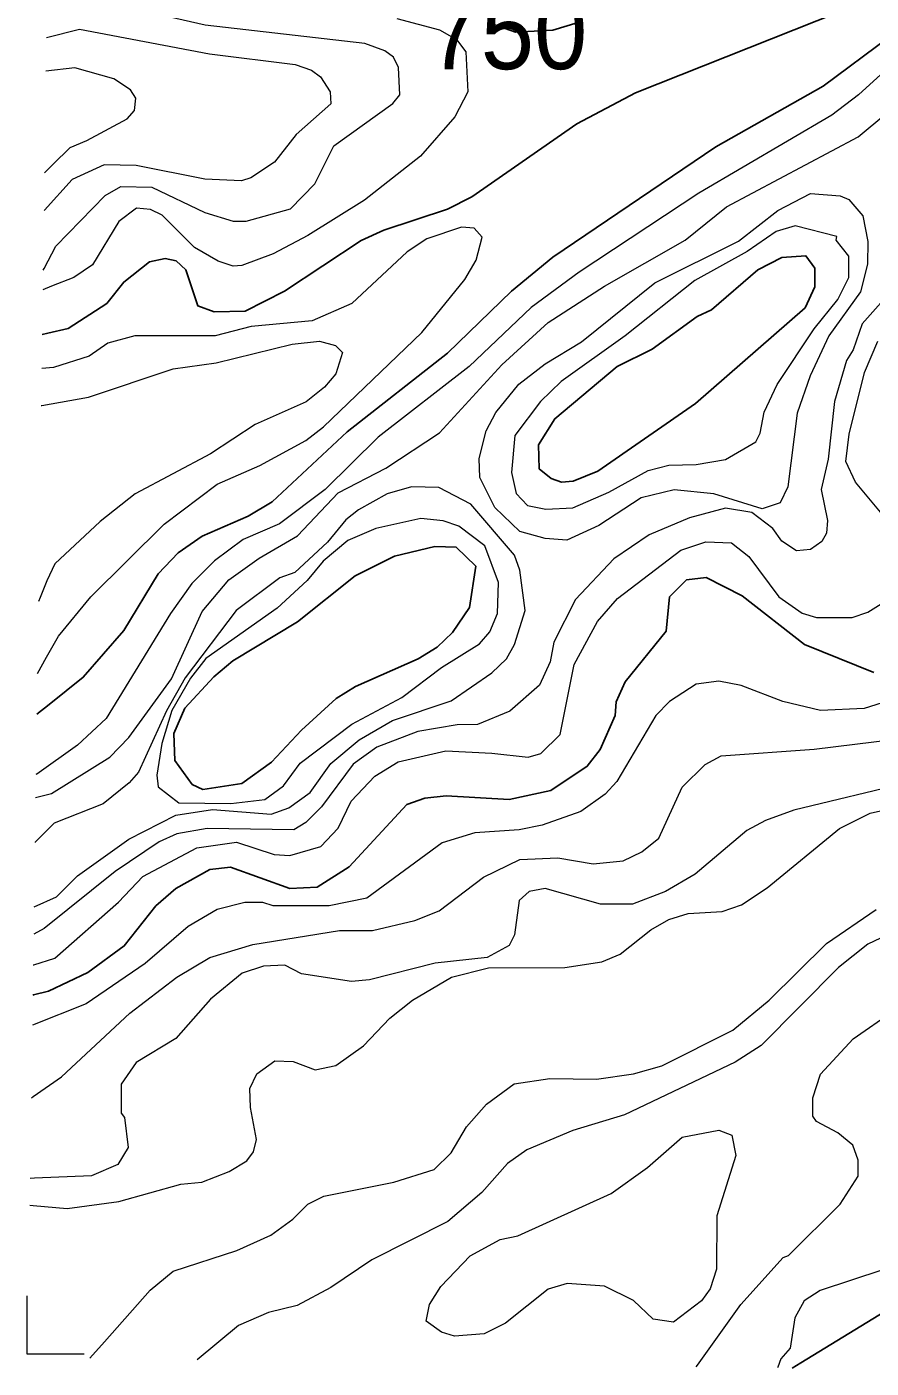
# Model space of a CAD drawing. Extents: x 763.2 to 816.8, y 7896.5 to 7952.7.
# Drawn here: x 763.19 to 764.982, y 7897.272 to 7900.119 of the extents above; entities that cross this region are included whole.
import ezdxf
from ezdxf.enums import TextEntityAlignment as Align

# ---------------------------------------------------------------- set-up
doc = ezdxf.new("R2010")
doc.units = 0
doc.header["$LTSCALE"] = 0.064
for name, color, linetype, lineweight in [('1', 7, 'Continuous', 25), ('2', 7, 'Continuous', 13), ('63', 7, 'Continuous', 13)]:
    doc.layers.add(name, color=color, linetype=linetype, lineweight=lineweight)
doc.layers.add('61', color=7, linetype='Continuous')

msp = doc.modelspace()

# ---------------------------------------------------------------- linework, layer by layer
at = {"layer": '1'}
for points in [[(765.2023, 7900.1889), (765.0206, 7900.0974), (764.8799, 7899.9927), (764.6523, 7899.8643), (764.3067, 7899.6301), (764.2184, 7899.5579), (764.0827, 7899.4258), (763.8702, 7899.2592), (763.7105, 7899.1107), (763.6598, 7899.0801), (763.562, 7899.0376), (763.5114, 7899.0022), (763.4688, 7898.9577), (763.3956, 7898.8377), (763.3097, 7898.7383), (763.2375, 7898.6808), (763.2112, 7898.6599)], [(763.2227, 7899.4656), (763.2344, 7899.4683), (763.2778, 7899.4783), (763.3598, 7899.5316), (763.3958, 7899.5769), (763.4504, 7899.6202), (763.4839, 7899.627), (763.5068, 7899.6222), (763.5276, 7899.6032), (763.5527, 7899.5264), (763.5876, 7899.5137), (763.6532, 7899.5152), (763.737, 7899.5574), (763.8997, 7899.6651), (763.9475, 7899.6872), (764.0828, 7899.7318), (764.1347, 7899.7579), (764.3572, 7899.9132), (764.4816, 7899.979), (764.9149, 7900.1509)], [(764.3602, 7900.1278), (764.3066, 7900.1116), (764.2273, 7900.1075), (764.1835, 7900.123)], [(763.2028, 7898.0637), (763.2039, 7898.064), (763.2363, 7898.0724), (763.3196, 7898.1114), (763.3967, 7898.1681), (763.464, 7898.2531), (763.5064, 7898.2898), (763.5785, 7898.3302), (763.6221, 7898.3351), (763.7485, 7898.2898), (763.8064, 7898.2928), (763.874, 7898.3362), (763.9966, 7898.4683), (764.0346, 7898.4817), (764.0798, 7898.4867), (764.2134, 7898.4786), (764.3023, 7898.4978), (764.3795, 7898.5493), (764.407, 7898.5848), (764.4384, 7898.6572), (764.4409, 7898.6864), (764.4602, 7898.7284), (764.5467, 7898.8363), (764.5541, 7898.9091), (764.5902, 7898.9452), (764.6315, 7898.9503), (764.7083, 7898.9108), (764.8408, 7898.8077), (764.9877, 7898.7483)], [(765.2865, 7898.4746), (765.2646, 7898.4497), (765.2575, 7898.4136), (765.263, 7898.4013), (765.3189, 7898.3901), (765.3894, 7898.4149), (765.5161, 7898.4868), (765.7045, 7898.6435), (765.7826, 7898.6814), (765.8542, 7898.6713), (765.8664, 7898.6475), (765.8457, 7898.5762), (765.7321, 7898.4812), (765.6742, 7898.4221), (765.615, 7898.3464), (765.5252, 7898.1825), (765.4318, 7898.0356), (765.3071, 7897.904), (765.206, 7897.7449), (765.1289, 7897.5484), (765.0877, 7897.4645), (765.0489, 7897.4158), (764.8329, 7897.2832), (764.8144, 7897.2719)]]:
    msp.add_lwpolyline(points, dxfattribs=at)
for points in [[(764.4427, 7899.3976), (764.5169, 7899.4348), (764.613, 7899.504), (764.6431, 7899.5178), (764.7418, 7899.6031), (764.7922, 7899.629), (764.8437, 7899.6325), (764.8622, 7899.6063), (764.8622, 7899.5667), (764.8418, 7899.5225), (764.6091, 7899.3196), (764.4016, 7899.1759), (764.3496, 7899.1546), (764.3245, 7899.1526), (764.303, 7899.1604), (764.2777, 7899.1804), (764.2761, 7899.2315), (764.3106, 7899.2871)], [(763.8874, 7898.7188), (764.0206, 7898.7773), (764.0608, 7898.8024), (764.0936, 7898.8336), (764.1296, 7898.8862), (764.1427, 7898.9741), (764.1009, 7899.0142), (764.0558, 7899.0157), (763.9703, 7898.9956), (763.8867, 7898.9535), (763.7642, 7898.8561), (763.627, 7898.7728), (763.5869, 7898.7394), (763.5254, 7898.6729), (763.5021, 7898.6189), (763.5041, 7898.5618), (763.541, 7898.5105), (763.5638, 7898.5003), (763.646, 7898.5131), (763.7096, 7898.558), (763.7728, 7898.6261), (763.8465, 7898.6933)]]:
    msp.add_lwpolyline(points, close=True, dxfattribs=at)
at = {"layer": '2'}
for points in [[(763.2247, 7899.6025), (763.2265, 7899.6059), (763.2519, 7899.653), (763.3563, 7899.7609), (763.3896, 7899.7796), (763.455, 7899.7788), (763.5677, 7899.7244), (763.6276, 7899.7063), (763.6553, 7899.7065), (763.7499, 7899.7328), (763.801, 7899.7852), (763.8414, 7899.8661), (763.9665, 7899.9559), (763.9817, 7899.9743), (763.9787, 7900.0326), (763.9683, 7900.0545), (763.9499, 7900.0681), (763.9075, 7900.0831), (763.5684, 7900.122), (763.4064, 7900.159), (763.3564, 7900.1779), (763.3128, 7900.1619), (763.2325, 7900.1554)], [(763.9752, 7900.1367), (764.066, 7900.1126), (764.1017, 7900.0922), (764.1216, 7900.0659), (764.1262, 7899.9811), (764.0981, 7899.9276), (764.0258, 7899.8439), (763.9067, 7899.7511), (763.7865, 7899.6759), (763.7127, 7899.6373), (763.6464, 7899.6122), (763.6281, 7899.611), (763.5961, 7899.6212), (763.546, 7899.6507), (763.4773, 7899.7193), (763.4528, 7899.7307), (763.4225, 7899.7341), (763.385, 7899.7056), (763.3297, 7899.6133), (763.2896, 7899.587), (763.2424, 7899.5682), (763.2241, 7899.5609)], [(763.2087, 7898.4828), (763.2423, 7898.4919), (763.3662, 7898.5685), (763.4065, 7898.6101), (763.497, 7898.7351), (763.562, 7898.8776), (763.6188, 7898.9453), (763.6828, 7898.9913), (763.7643, 7899.0387), (763.8511, 7899.1295), (763.9523, 7899.1821), (764.0661, 7899.2567), (764.1982, 7899.4016), (764.2963, 7899.4911), (764.4163, 7899.5685), (764.5871, 7899.666), (764.6749, 7899.7365), (764.9543, 7899.885), (765.0129, 7899.9338), (765.0931, 7900.0264), (765.1185, 7900.0452), (765.1961, 7900.0734), (765.2881, 7900.119)], [(763.2317, 7900.096), (763.3015, 7900.1137), (763.5779, 7900.0614), (763.7596, 7900.0387), (763.7939, 7900.0269), (763.8132, 7900.0128), (763.8336, 7899.981), (763.8352, 7899.955), (763.7614, 7899.8901), (763.716, 7899.8317), (763.6657, 7899.798), (763.6459, 7899.7918), (763.5678, 7899.7951), (763.422, 7899.8241), (763.3541, 7899.826), (763.286, 7899.7945), (763.2276, 7899.7293), (763.2265, 7899.728)], [(765.1723, 7900.1208), (765.0898, 7900.0971), (764.9548, 7899.9742), (764.8989, 7899.9315)], [(763.2276, 7899.8086), (763.2455, 7899.8265), (763.2819, 7899.8628), (763.3174, 7899.8777), (763.4033, 7899.9235), (763.4183, 7899.9411), (763.4214, 7899.9672), (763.4098, 7899.9852), (763.3744, 7900.0082), (763.2916, 7900.0315), (763.2306, 7900.0243)], [(764.8989, 7899.9315), (764.6163, 7899.7654), (764.3621, 7899.5981), (764.2603, 7899.5229), (764.1285, 7899.3978), (763.936, 7899.2477)], [(763.2125, 7898.7466), (763.2318, 7898.7806), (763.2574, 7898.8257), (763.3262, 7898.9092), (763.4818, 7899.0632), (763.5943, 7899.1483), (763.6842, 7899.1876), (763.7825, 7899.2407), (763.8196, 7899.2696), (764.0284, 7899.4702), (764.1195, 7899.5825), (764.1434, 7899.6238), (764.1561, 7899.6721), (764.1394, 7899.6912), (764.1128, 7899.6932), (764.0392, 7899.669), (763.9972, 7899.6411), (763.8795, 7899.5315), (763.7959, 7899.4947), (763.6664, 7899.4826), (763.5896, 7899.4632), (763.4192, 7899.4628), (763.3621, 7899.4471), (763.3221, 7899.4201), (763.2463, 7899.3959), (763.2217, 7899.3936)], [(765.0361, 7899.5704), (764.9628, 7899.4887), (764.9437, 7899.4332), (764.9298, 7899.4107), (764.904, 7899.3239), (764.8906, 7899.2011), (764.8761, 7899.1367), (764.8891, 7899.0713), (764.8873, 7899.044), (764.8774, 7899.0261), (764.8531, 7899.0097), (764.8236, 7899.0064), (764.7923, 7899.0272), (764.7734, 7899.0543), (764.7286, 7899.0881), (764.6729, 7899.0973), (764.5965, 7899.0768), (764.5112, 7899.0405), (764.4356, 7898.9897), (764.3542, 7898.9032), (764.3083, 7898.8127), (764.3007, 7898.7711), (764.2784, 7898.7212), (764.2152, 7898.666), (764.1468, 7898.6382), (764.1031, 7898.6376), (764.0202, 7898.6229), (763.9331, 7898.5897), (763.8829, 7898.5538), (763.8155, 7898.4634), (763.782, 7898.4299), (763.7567, 7898.4147), (763.5731, 7898.4176), (763.5087, 7898.4061), (763.4709, 7898.389), (763.3777, 7898.326), (763.2268, 7898.2048), (763.2046, 7898.1929)], [(763.2206, 7899.3148), (763.2215, 7899.315), (763.321, 7899.3324), (763.5009, 7899.3928), (763.5916, 7899.4059), (763.7532, 7899.4452), (763.8115, 7899.4514), (763.845, 7899.4425), (763.8599, 7899.4277), (763.8457, 7899.3821), (763.8219, 7899.3541), (763.7826, 7899.3226), (763.6743, 7899.2747), (763.5796, 7899.2124), (763.4199, 7899.1277), (763.3455, 7899.0692), (763.2495, 7898.9787), (763.2326, 7898.9429), (763.2181, 7898.9076), (763.2147, 7898.8992)], [(765.009, 7899.0801), (764.949, 7899.1521), (764.9286, 7899.1964), (764.935, 7899.2542), (764.9679, 7899.3852), (764.996, 7899.4515)], [(763.936, 7899.2477), (763.823, 7899.1371), (763.7261, 7899.064), (763.6494, 7899.0304), (763.5882, 7898.9855), (763.5403, 7898.9376), (763.4946, 7898.8733), (763.3582, 7898.6507), (763.2975, 7898.5945), (763.2112, 7898.5329), (763.2094, 7898.5316)], [(763.2054, 7898.2507), (763.2059, 7898.2509), (763.2527, 7898.272), (763.2977, 7898.317), (763.4068, 7898.3946), (763.5063, 7898.4454), (763.5843, 7898.4573), (763.7084, 7898.4475), (763.7458, 7898.461), (763.7911, 7898.4936), (763.8352, 7898.5553), (763.8953, 7898.6055), (763.9661, 7898.6464), (764.0907, 7898.6879), (764.1769, 7898.7477), (764.2081, 7898.7773), (764.2249, 7898.8079), (764.248, 7898.8797), (764.2364, 7898.9657), (764.2253, 7898.9973), (764.1321, 7899.1058), (764.0641, 7899.141), (764.0063, 7899.1427), (763.955, 7899.1274), (763.8937, 7899.0936), (763.8674, 7899.0723), (763.8284, 7899.0253), (763.7587, 7898.9608), (763.7267, 7898.9492), (763.6343, 7898.8801), (763.5263, 7898.7368), (763.4862, 7898.6667), (763.4268, 7898.5372), (763.4074, 7898.514), (763.3519, 7898.4694), (763.2483, 7898.4283), (763.2079, 7898.3883), (763.2074, 7898.3878)], [(763.2037, 7898.1277), (763.2046, 7898.128), (763.2491, 7898.1424), (763.3847, 7898.261), (763.4359, 7898.3151), (763.5507, 7898.3764), (763.6349, 7898.3881), (763.715, 7898.3622), (763.7485, 7898.3603), (763.8141, 7898.3788), (763.8511, 7898.4183), (763.8786, 7898.4751), (763.9289, 7898.5283), (763.9781, 7898.5587), (764.0796, 7898.5819), (764.1768, 7898.5774), (764.2541, 7898.569), (764.2812, 7898.5765), (764.3217, 7898.6169), (764.3518, 7898.7654), (764.401, 7898.8566), (764.4435, 7898.9055), (764.5781, 7899.0083), (764.6313, 7899.0256), (764.6857, 7899.0238), (764.7226, 7898.9948), (764.7861, 7898.9088), (764.8355, 7898.8745), (764.866, 7898.8649), (764.9416, 7898.8649), (764.9751, 7898.8767), (765.0205, 7898.9044)], [(765.0434, 7898.6958), (764.9671, 7898.6717), (764.8746, 7898.6679), (764.7944, 7898.6871), (764.7062, 7898.7206), (764.6584, 7898.73), (764.6103, 7898.7236), (764.5543, 7898.687), (764.5252, 7898.6571), (764.4421, 7898.5172), (764.4173, 7898.4902), (764.3658, 7898.4537), (764.2837, 7898.4242), (764.235, 7898.4146), (764.1409, 7898.4079), (764.0713, 7898.3867), (763.9114, 7898.2697), (763.8314, 7898.2535), (763.7131, 7898.2535), (763.6911, 7898.26), (763.6526, 7898.2599), (763.5941, 7898.2451), (763.5322, 7898.2093), (763.4415, 7898.1307), (763.3157, 7898.0455), (763.2019, 7898)], [(765.2665, 7898.7412), (765.216, 7898.6496), (765.1688, 7898.5827), (765.1267, 7898.5457), (765.0647, 7898.5154), (764.8181, 7898.456)], [(763.1997, 7897.8456), (763.2035, 7897.8483), (763.2636, 7897.8905), (763.4089, 7898.0254), (763.5081, 7898.1018), (763.5783, 7898.1435), (763.6696, 7898.1712), (763.8537, 7898.2007), (763.9234, 7898.2011), (764.0133, 7898.2218), (764.0653, 7898.2428), (764.1595, 7898.3142), (764.2361, 7898.3516), (764.3171, 7898.3553), (764.3918, 7898.3422), (764.4559, 7898.349), (764.495, 7898.3676), (764.5312, 7898.3971), (764.5806, 7898.5051), (764.6298, 7898.5532), (764.6634, 7898.5718), (764.861, 7898.5856), (765.0337, 7898.6069)], [(763.1965, 7897.6176), (763.2036, 7897.617), (763.2759, 7897.611), (763.3855, 7897.6254), (763.5168, 7897.6622), (763.5612, 7897.6668), (763.6197, 7897.6895), (763.6569, 7897.7119), (763.671, 7897.7309), (763.6777, 7897.7571), (763.6647, 7897.8252), (763.6634, 7897.8658), (763.6785, 7897.8967), (763.7162, 7897.9245), (763.7551, 7897.9231), (763.8018, 7897.9051), (763.8457, 7897.9145), (763.9046, 7897.9561), (763.9606, 7898.0151), (764.0088, 7898.0533), (764.0912, 7898.102), (764.17, 7898.1219), (764.3318, 7898.122), (764.4106, 7898.134), (764.4492, 7898.1504), (764.5145, 7898.2024), (764.5528, 7898.224), (764.5933, 7898.2369), (764.6661, 7898.2411), (764.7066, 7898.2552), (764.7615, 7898.2917), (764.9148, 7898.4173), (764.9798, 7898.4499), (765.0271, 7898.4605)], [(764.8181, 7898.456), (764.7576, 7898.4342), (764.7182, 7898.4128), (764.6085, 7898.3204), (764.5453, 7898.2837), (764.4756, 7898.257), (764.4074, 7898.2565), (764.2901, 7898.2896), (764.256, 7898.2833), (764.235, 7898.2642), (764.2249, 7898.1917), (764.2138, 7898.1688), (764.1669, 7898.1433), (764.0569, 7898.1316), (763.9175, 7898.096), (763.8791, 7898.0925), (763.773, 7898.1089), (763.7375, 7898.1269), (763.692, 7898.125), (763.6467, 7898.1103), (763.5798, 7898.0551), (763.5065, 7897.9719), (763.4224, 7897.9206), (763.3905, 7897.875), (763.3903, 7897.8128), (763.397, 7897.804), (763.405, 7897.7406), (763.3832, 7897.7043), (763.3271, 7897.6799), (763.206, 7897.675), (763.1973, 7897.6746)], [(763.3239, 7897.2931), (763.3546, 7897.3277), (763.4517, 7897.4372), (763.5005, 7897.4775), (763.6355, 7897.5217), (763.7079, 7897.5544), (763.7549, 7897.5881), (763.7867, 7897.6197), (763.8202, 7897.6368), (763.9687, 7897.6668), (764.0544, 7897.6933), (764.0905, 7897.7289), (764.1231, 7897.7844), (764.1655, 7897.8322), (764.2241, 7897.8756), (764.3, 7897.8869), (764.3993, 7897.8854), (764.4776, 7897.8967), (764.5374, 7897.9133), (764.6883, 7897.9892), (764.7657, 7898.053), (764.8874, 7898.1729), (764.9926, 7898.2452)], [(765.0411, 7898.2027), (764.9752, 7898.1715), (764.9125, 7898.1224), (764.7487, 7897.9569), (764.6935, 7897.9212), (764.4585, 7897.8098), (764.3487, 7897.7763), (764.2509, 7897.7353), (764.2104, 7897.706), (764.1555, 7897.6448), (764.0838, 7897.583), (763.9222, 7897.502), (763.835, 7897.443), (763.7636, 7897.4047), (763.7027, 7897.3904), (763.6395, 7897.3622), (763.5518, 7897.2899)], [(764.6108, 7897.2748), (764.6131, 7897.278), (764.7051, 7897.4068), (764.7952, 7897.5068), (764.8067, 7897.511), (764.9162, 7897.6203), (764.9543, 7897.6794), (764.9546, 7897.7134), (764.9432, 7897.7454), (764.911, 7897.7715), (764.8663, 7897.7954), (764.858, 7897.807), (764.8581, 7897.8456), (764.8743, 7897.8961), (764.9435, 7897.9707), (765.0293, 7898.0302)], [(765.0068, 7897.4808), (764.874, 7897.4371), (764.8401, 7897.4149), (764.8199, 7897.3784), (764.8101, 7897.3144), (764.7904, 7897.2916), (764.784, 7897.274), (764.7834, 7897.2723)]]:
    msp.add_lwpolyline(points, dxfattribs=at)
for points in [[(764.9159, 7899.7603), (764.9347, 7899.7526), (764.9642, 7899.7174), (764.9748, 7899.6629), (764.9743, 7899.6152), (764.9593, 7899.5561), (764.8924, 7899.463), (764.8525, 7899.3779), (764.8247, 7899.2989), (764.8051, 7899.1426), (764.7891, 7899.1087), (764.7509, 7899.0961), (764.6478, 7899.1274), (764.5637, 7899.1359), (764.494, 7899.1192), (764.4042, 7899.0605), (764.3363, 7899.0292), (764.2901, 7899.0326), (764.2367, 7899.0475), (764.1836, 7899.0987), (764.1513, 7899.1621), (764.1498, 7899.2024), (764.1647, 7899.2615), (764.1857, 7899.3003), (764.2339, 7899.36), (764.2903, 7899.4034), (764.367, 7899.4503), (764.5231, 7899.5755), (764.7003, 7899.664), (764.784, 7899.7292), (764.8531, 7899.7651)], [(764.7373, 7899.2381), (764.7467, 7899.2566), (764.7547, 7899.3009), (764.7823, 7899.3595), (764.8612, 7899.4778), (764.9113, 7899.54), (764.9349, 7899.5864), (764.9349, 7899.6317), (764.9079, 7899.6663), (764.9095, 7899.6735), (764.8206, 7899.6961), (764.7802, 7899.6845), (764.7191, 7899.6418), (764.6077, 7899.5805), (764.4601, 7899.4631), (764.3238, 7899.366), (764.2801, 7899.3238), (764.2256, 7899.2516), (764.2185, 7899.1728), (764.2288, 7899.128), (764.2526, 7899.1028), (764.2915, 7899.0949), (764.3486, 7899.098), (764.4256, 7899.1309), (764.5085, 7899.1772), (764.5523, 7899.1882), (764.6107, 7899.19), (764.6728, 7899.2003)], [(764.1889, 7898.8737), (764.191, 7898.9395), (764.1623, 7899.0172), (764.1072, 7899.0591), (764.0739, 7899.0702), (764.0265, 7899.0749), (763.9307, 7899.0542), (763.8715, 7899.0282), (763.8191, 7898.985), (763.7853, 7898.9436), (763.721, 7898.8851), (763.5699, 7898.7781), (763.5373, 7898.7362), (763.4976, 7898.6678), (763.4762, 7898.598), (763.4662, 7898.5306), (763.4687, 7898.5055), (763.5127, 7898.472), (763.6229, 7898.4703), (763.6955, 7898.4789), (763.7347, 7898.5081), (763.7699, 7898.5557), (763.8797, 7898.6384), (763.9862, 7898.6952), (764.0702, 7898.7592), (764.1511, 7898.8092), (764.1729, 7898.8349)], [(764.2319, 7897.5528), (764.43, 7897.6423), (764.5073, 7897.6975), (764.5808, 7897.7622), (764.659, 7897.7767), (764.6861, 7897.7665), (764.6951, 7897.7233), (764.6546, 7897.5949), (764.6536, 7897.4817), (764.6401, 7897.4404), (764.6216, 7897.4145), (764.5623, 7897.3698), (764.5196, 7897.3761), (764.4776, 7897.4155), (764.4163, 7897.4462), (764.337, 7897.4514), (764.2967, 7897.4394), (764.206, 7897.3675), (764.1604, 7897.3446), (764.0975, 7897.3398), (764.07, 7897.3483), (764.0377, 7897.372), (764.0445, 7897.4071), (764.0685, 7897.4455), (764.131, 7897.5101), (764.1949, 7897.5447)]]:
    msp.add_lwpolyline(points, close=True, dxfattribs=at)
at = {"layer": '63'}
msp.add_lwpolyline([(763.19, 7897.4257), (763.19, 7897.3025), (763.3114, 7897.3025)], dxfattribs=at)

# ---------------------------------------------------------------- texts
at = {"layer": '61', "width": 0.95}
msp.add_text('750', height=0.16, rotation=0.027, dxfattribs=at).set_placement((764.21, 7900.0289), align=Align.CENTER)

doc.saveas('drawing.dxf')
